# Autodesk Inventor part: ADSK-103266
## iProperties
Created: 2000-11
Part Number: ADSK-103266
Description: Hexagon Socket Countersunk Head Screw
Document SubType Name: Modeling
Standard: ISO 10642 - M5 x  30
Designer: donna
Density: 1 g/cm^3
Control State: 0
Master: False
Checked Out: False
Shininess: 0.0
Density: 0.0
Volumn: 0.0
Area: 0.0
PropertySet Name: Model Information
Author: donna
